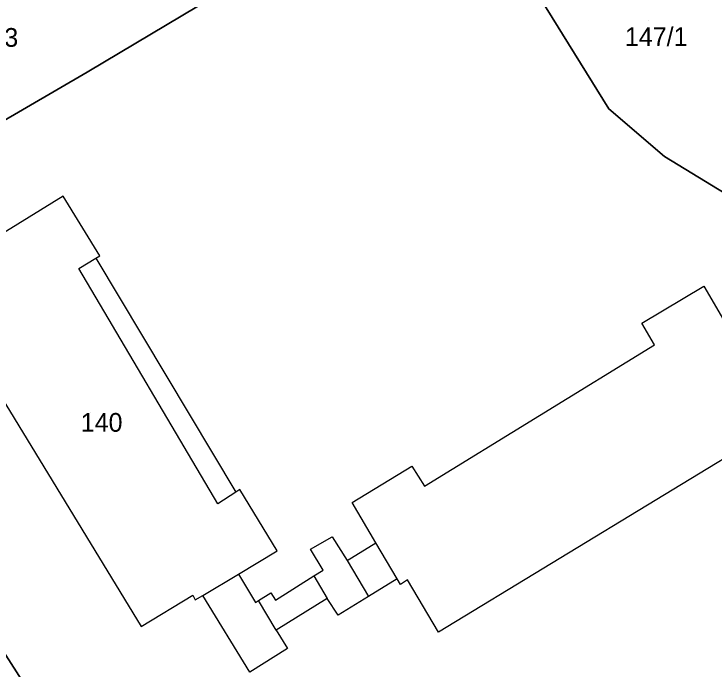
# Model space of a CAD drawing. Extents: x -263943 to -261149, y -1236934 to -1230686.
# Drawn here: x -262618.9 to -262544.1, y -1235851.1 to -1235781 of the extents above; entities that cross this region are included whole.
import ezdxf

# ---------------------------------------------------------------- set-up
doc = ezdxf.new("R2010")
doc.units = 0
for name, color, linetype in [('body_kn', 7, 'Continuous'), ('kladpar_druhypozemkov', 7, 'Continuous'), ('kladpar_hranice', 7, 'Continuous'), ('kladpar_parcelnecisla', 7, 'Continuous'), ('kladpar_plochy', 7, 'Continuous'), ('zappar_hrandruhpozemk', 7, 'Continuous')]:
    doc.layers.add(name, color=color, linetype=linetype)

msp = doc.modelspace()

# ---------------------------------------------------------------- linework, layer by layer
at = {"layer": 'body_kn'}
for p, q in [((-262611.04, -1235787.25), (-262611.04, -1235787.25)), ((-262555.31, -1235791.15), (-262555.31, -1235791.15)), ((-262549.37, -1235796.26), (-262549.37, -1235796.26)), ((-262613.61, -1235800.48), (-262613.61, -1235800.48)), ((-262609.72, -1235806.85), (-262609.72, -1235806.85)), ((-262610.13, -1235807.1), (-262610.13, -1235807.1)), ((-262610.13, -1235807.1), (-262610.13, -1235807.1)), ((-262611.93, -1235808.2), (-262611.93, -1235808.2)), ((-262545.15, -1235810.09), (-262545.15, -1235810.09)), ((-262545.15, -1235810.09), (-262545.15, -1235810.09)), ((-262551.78, -1235814.06), (-262551.78, -1235814.06)), ((-262550.43, -1235816.35), (-262550.43, -1235816.35)), ((-262576.37, -1235829.34), (-262576.37, -1235829.34)), ((-262575.01, -1235831.46), (-262575.01, -1235831.46)), ((-262595.16, -1235832.1), (-262595.16, -1235832.1)), ((-262594.73, -1235831.83), (-262594.73, -1235831.83)), ((-262597.11, -1235833.35), (-262597.11, -1235833.35)), ((-262582.75, -1235833.22), (-262582.75, -1235833.22)), ((-262584.88, -1235836.86), (-262584.88, -1235836.86)), ((-262580.21, -1235837.52), (-262580.21, -1235837.52)), ((-262580.21, -1235837.52), (-262580.21, -1235837.52)), ((-262590.75, -1235838.37), (-262590.75, -1235838.37)), ((-262587.18, -1235838.21), (-262587.18, -1235838.21)), ((-262583.27, -1235839.41), (-262583.27, -1235839.41)), ((-262583.27, -1235839.41), (-262583.27, -1235839.41)), ((-262585.82, -1235840.42), (-262585.82, -1235840.42)), ((-262594.89, -1235840.85), (-262594.89, -1235840.85)), ((-262586.82, -1235841.05), (-262586.82, -1235841.05)), ((-262586.82, -1235841.05), (-262586.82, -1235841.05)), ((-262577.94, -1235841.35), (-262577.94, -1235841.35)), ((-262577.58, -1235841.97), (-262577.58, -1235841.97)), ((-262576.82, -1235841.47), (-262576.82, -1235841.47)), ((-262591.43, -1235842.87), (-262591.43, -1235842.87)), ((-262599.76, -1235843.1), (-262599.76, -1235843.1)), ((-262599.76, -1235843.1), (-262599.76, -1235843.1)), ((-262599.51, -1235843.61), (-262599.51, -1235843.61)), ((-262598.71, -1235843.13), (-262598.71, -1235843.13)), ((-262598.71, -1235843.13), (-262598.71, -1235843.13)), ((-262592.73, -1235843.68), (-262592.73, -1235843.68)), ((-262590.93, -1235843.63), (-262590.93, -1235843.63)), ((-262585.4, -1235843.48), (-262585.4, -1235843.48)), ((-262580.99, -1235843.25), (-262580.99, -1235843.25)), ((-262593.05, -1235843.88), (-262593.05, -1235843.88)), ((-262584.22, -1235845.26), (-262584.22, -1235845.26)), ((-262605.29, -1235846.47), (-262605.29, -1235846.47)), ((-262590.85, -1235846.85), (-262590.85, -1235846.85)), ((-262590.85, -1235846.85), (-262590.85, -1235846.85)), ((-262573.51, -1235847.07), (-262573.51, -1235847.07)), ((-262589.66, -1235848.81), (-262589.66, -1235848.81))]:
    msp.add_line(p, q, dxfattribs=at)
at = {"layer": 'kladpar_druhypozemkov'}
for p, q in [((-262551.12, -1235781.7), (-262551.12, -1235781.7)), ((-262610.67, -1235823.55), (-262610.67, -1235823.55))]:
    msp.add_line(p, q, dxfattribs=at)
at = {"layer": 'kladpar_hranice'}
for points in [[(-262543.94, -1235745.11), (-262545.68, -1235746.14), (-262549, -1235748.17), (-262549.6, -1235747.32), (-262559.32, -1235753.33), (-262559.74, -1235753.59), (-262567.06, -1235758.12), (-262570.55, -1235760.29), (-262573.59, -1235762.17), (-262572.32, -1235764.21), (-262575.73, -1235766.24), (-262576.07, -1235768.53), (-262582.11, -1235772.41), (-262583.9, -1235771.05), (-262611.04, -1235787.25), (-262646.33, -1235807.76)], [(-262531.78, -1235798.18), (-262536.63, -1235801.05), (-262539.95, -1235801.97), (-262549.37, -1235796.26), (-262555.31, -1235791.15), (-262561.99, -1235780.36), (-262572.32, -1235764.21), (-262573.59, -1235762.17), (-262570.55, -1235760.29), (-262569.21, -1235762.34), (-262571.73, -1235763.96), (-262570.81, -1235765.31), (-262567.49, -1235770.17), (-262565.09, -1235768.67), (-262564.94, -1235768.9), (-262554.5, -1235775.12), (-262548.44, -1235771.06), (-262544.99, -1235776.68), (-262539.2, -1235786.1), (-262531.78, -1235798.18)], [(-262576.07, -1235768.53), (-262575.73, -1235766.24), (-262572.32, -1235764.21), (-262561.99, -1235780.36), (-262555.31, -1235791.15), (-262549.37, -1235796.26), (-262539.95, -1235801.97), (-262536.63, -1235801.05), (-262531.78, -1235798.18), (-262515.86, -1235823.92), (-262489.14, -1235866.73)], [(-262605.67, -1235871.49), (-262620.33, -1235848.64), (-262635.19, -1235825.26), (-262636.43, -1235823.31), (-262646.33, -1235807.76), (-262611.04, -1235787.25), (-262583.9, -1235771.05), (-262582.11, -1235772.41), (-262576.07, -1235768.53)], [(-262600.26, -1235890.16), (-262602.47, -1235887.11), (-262614.02, -1235885.12), (-262627.27, -1235884.15), (-262628.97, -1235883.38), (-262631.93, -1235878.88), (-262633.21, -1235879.47), (-262636.85, -1235873.86), (-262631.41, -1235869.64), (-262637.59, -1235859.19), (-262629.77, -1235854.29), (-262620.33, -1235848.64), (-262605.67, -1235871.49), (-262596.01, -1235886.87), (-262600.26, -1235890.16)]]:
    msp.add_lwpolyline(points, dxfattribs=at)
at = {"layer": 'kladpar_plochy'}
for points in [[(-262543.94, -1235745.11), (-262545.68, -1235746.14), (-262549, -1235748.17), (-262549.6, -1235747.32), (-262559.32, -1235753.33), (-262559.74, -1235753.59), (-262567.06, -1235758.12), (-262570.55, -1235760.29), (-262573.59, -1235762.17), (-262572.32, -1235764.21), (-262575.73, -1235766.24), (-262576.07, -1235768.53), (-262582.11, -1235772.41), (-262583.9, -1235771.05), (-262611.04, -1235787.25), (-262646.33, -1235807.76)], [(-262605.67, -1235871.49), (-262620.33, -1235848.64), (-262635.19, -1235825.26), (-262636.43, -1235823.31), (-262646.33, -1235807.76), (-262611.04, -1235787.25), (-262583.9, -1235771.05), (-262582.11, -1235772.41), (-262576.07, -1235768.53), (-262575.73, -1235766.24), (-262572.32, -1235764.21), (-262561.99, -1235780.36), (-262555.31, -1235791.15), (-262549.37, -1235796.26), (-262539.95, -1235801.97), (-262536.63, -1235801.05), (-262531.78, -1235798.18), (-262515.86, -1235823.92), (-262489.14, -1235866.73)]]:
    msp.add_lwpolyline(points, dxfattribs=at)
for points in [[(-262531.78, -1235798.18), (-262536.63, -1235801.05), (-262539.95, -1235801.97), (-262549.37, -1235796.26), (-262555.31, -1235791.15), (-262561.99, -1235780.36), (-262572.32, -1235764.21), (-262573.59, -1235762.17), (-262570.55, -1235760.29), (-262569.21, -1235762.34), (-262571.73, -1235763.96), (-262570.81, -1235765.31), (-262567.49, -1235770.17), (-262565.09, -1235768.67), (-262564.94, -1235768.9), (-262554.5, -1235775.12), (-262548.44, -1235771.06), (-262544.99, -1235776.68), (-262539.2, -1235786.1)], [(-262600.26, -1235890.16), (-262602.47, -1235887.11), (-262614.02, -1235885.12), (-262627.27, -1235884.15), (-262628.97, -1235883.38), (-262631.93, -1235878.88), (-262633.21, -1235879.47), (-262636.85, -1235873.86), (-262631.41, -1235869.64), (-262637.59, -1235859.19), (-262629.77, -1235854.29), (-262620.33, -1235848.64), (-262605.67, -1235871.49), (-262596.01, -1235886.87)]]:
    msp.add_lwpolyline(points, close=True, dxfattribs=at)
at = {"layer": 'zappar_hrandruhpozemk'}
for p, q in [((-262610.13, -1235807.1), (-262595.16, -1235832.1)), ((-262597.11, -1235833.35), (-262611.93, -1235808.2)), ((-262627.56, -1235809.94), (-262605.29, -1235846.47)), ((-262575.01, -1235831.46), (-262550.43, -1235816.35)), ((-262577.94, -1235841.35), (-262580.21, -1235837.52)), ((-262583.27, -1235839.41), (-262580.99, -1235843.25)), ((-262598.71, -1235843.13), (-262594.89, -1235840.85)), ((-262586.82, -1235841.05), (-262585.4, -1235843.48)), ((-262605.29, -1235846.47), (-262599.76, -1235843.1)), ((-262590.85, -1235846.85), (-262592.73, -1235843.68))]:
    msp.add_line(p, q, dxfattribs=at)
for points in [[(-262611.93, -1235808.2), (-262610.13, -1235807.1), (-262609.72, -1235806.85), (-262613.61, -1235800.48), (-262622.12, -1235805.71), (-262621.78, -1235806.31), (-262627.56, -1235809.94)], [(-262545.15, -1235810.09), (-262539.56, -1235819.69), (-262540.07, -1235820.03), (-262537.27, -1235825.04), (-262573.51, -1235847.07), (-262576.82, -1235841.47), (-262577.58, -1235841.97), (-262577.94, -1235841.35)], [(-262550.43, -1235816.35), (-262551.78, -1235814.06), (-262545.15, -1235810.09)], [(-262580.21, -1235837.52), (-262582.75, -1235833.22), (-262576.37, -1235829.34), (-262575.01, -1235831.46)], [(-262594.89, -1235840.85), (-262590.75, -1235838.37), (-262594.73, -1235831.83), (-262595.16, -1235832.1), (-262597.11, -1235833.35)], [(-262594.89, -1235840.85), (-262593.05, -1235843.88), (-262592.73, -1235843.68), (-262591.43, -1235842.87), (-262590.93, -1235843.63), (-262586.82, -1235841.05), (-262585.82, -1235840.42), (-262587.18, -1235838.21), (-262584.88, -1235836.86), (-262583.27, -1235839.41), (-262580.21, -1235837.52)], [(-262577.94, -1235841.35), (-262580.99, -1235843.25), (-262584.22, -1235845.26), (-262585.4, -1235843.48), (-262590.85, -1235846.85), (-262589.66, -1235848.81), (-262593.66, -1235851.34), (-262598.71, -1235843.13)], [(-262599.76, -1235843.1), (-262599.51, -1235843.61), (-262598.71, -1235843.13)]]:
    msp.add_lwpolyline(points, dxfattribs=at)

# ---------------------------------------------------------------- texts
at = {"layer": 'kladpar_parcelnecisla'}
msp.add_text('1583', height=2, rotation=360, dxfattribs=at).set_placement((-262624.37, -1235784.53))
for s, p in [('147/1', (-262553.593, -1235784.45)), ('140', (-262611.741, -1235825.65))]:
    msp.add_text(s, height=2, dxfattribs=at).set_placement(p)

doc.saveas('drawing.dxf')
